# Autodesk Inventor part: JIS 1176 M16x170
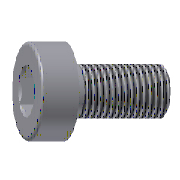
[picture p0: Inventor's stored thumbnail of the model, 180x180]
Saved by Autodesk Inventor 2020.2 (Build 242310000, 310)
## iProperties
Manager: www.cadconsulting.pl
Company: Fabian Stasiak CAD Consulting
Created: 2014-02
Part Number: JIS 1176 M16x170
Material: Stal, miękka
Description: Cylinder Head Cap Screw
Document SubType Name: Modeling
Designer: F.Stasiak
Standard Revision: 1
Language: pl-PL
Size Designation: M16x170
Categories: <MemberInstance><Categories><Category DisplayName="Forma wtryskowa" InternalName="349578f2-f4d4-4954-8c09-8e99297a61c0" Mnemonic="MOLD"><Category DisplayName="C
Mass: 0.133121 g
Surface Area: 2.01441 cm^2
Volume: 0.133121 cm^3
Density: 7.85 g/cm^3
Appearance: Częściowo polerowana
Catalog Web Link: www.expertbooks.pl
IsCustomPart: 0
Author: F.Stasiak
Subject: Zbiór ćwiczeń. Autodesk Inventor 2020. Kurs Professional
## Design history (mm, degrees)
sketch "Sketch1"
  geometry: L1 (0, -207.2)-(0, 53.2) reference; L2 (8.083, 16)-(12, 16); L3 (12, 16)-(12, 0); L4 (12, 0)-(8, 0); L5 (8, 0)-(8, -170); L6 (8, -170)-(0, -170); L7 (0, 3.794)-(0, -170); L8 (0, 3.794)-(7, 8); L9 (7, 8)-(7, 14.917); L10 (7, 14.917)-(8.083, 16); 1 further point
  constraints: 18 end point, 4 vertical, 3 horizontal, 2 point on line
  dimensions: "d0" = 24 diameter of L3 L1 (= dk); "d1" = 16 distance between parallel lines of L4 L2 (= k); "d2" = 16 diameter of L5 L1 (= d); "d3" = 170 distance between parallel lines of L6 L4 (= L); "d4" = 59 deg angle of L1 L8; "d5" = 45 deg angle of L1 L10; "d6" = 14 diameter of L9 L1 (= sw); "d7" = 16.16581 diameter of L2.start L1 (= 1.1547 x sw); "d8" = 8 distance from line of L8.end L2 (= t)
revolve "Revolution1" sketch "Sketch1" stored, may be unused: angle "d44" = 90 deg
sketch "Sketch2"
  geometry: L1 (0, 8.083)-(7, 4.041); L2 (7, 4.041)-(7, -4.041); L3 (7, -4.041)-(0, -8.083); L4 (0, -8.083)-(-7, -4.041); L5 (-7, -4.041)-(-7, 4.041); L6 (-7, 4.041)-(0, 8.083); 3 further points
  constraints: 12 end point, 2 vertical alignment, 1 coincident, 14 other
extrude "Extrusion1" cut sketch "Sketch2" taper "d9" = 0 deg; stored distance "d45" = 10
thread "Thread1" dims "d10" = 44 (= b), "d11" = 0
chamfer "Chamfer1" distance "d12" = 1 (= 0.5 x P); stored, may be unused: second distance "d50" = 2, angle "d51" = 45 deg
fillet "Fillet1" dims "d13" = 1 (= 0.5 x P)
body "Solid1"
other parameters: "d" = 16 [user parameter; used in 1 equation term], "L" = 170 [user parameter; used in 1 equation term], "dk" = 24 [user parameter; used in 1 equation term], "b" = 44 [user parameter; used in 1 equation term], "k" = 16 [user parameter; used in 1 equation term], "sw" = 14 [user parameter; used in 2 equation terms], "t" = 8 [user parameter; used in 1 equation term], "P" = 2 [user parameter; used in 2 equation terms], "d14" = 0, "d15" = 0, "d55" = 0
